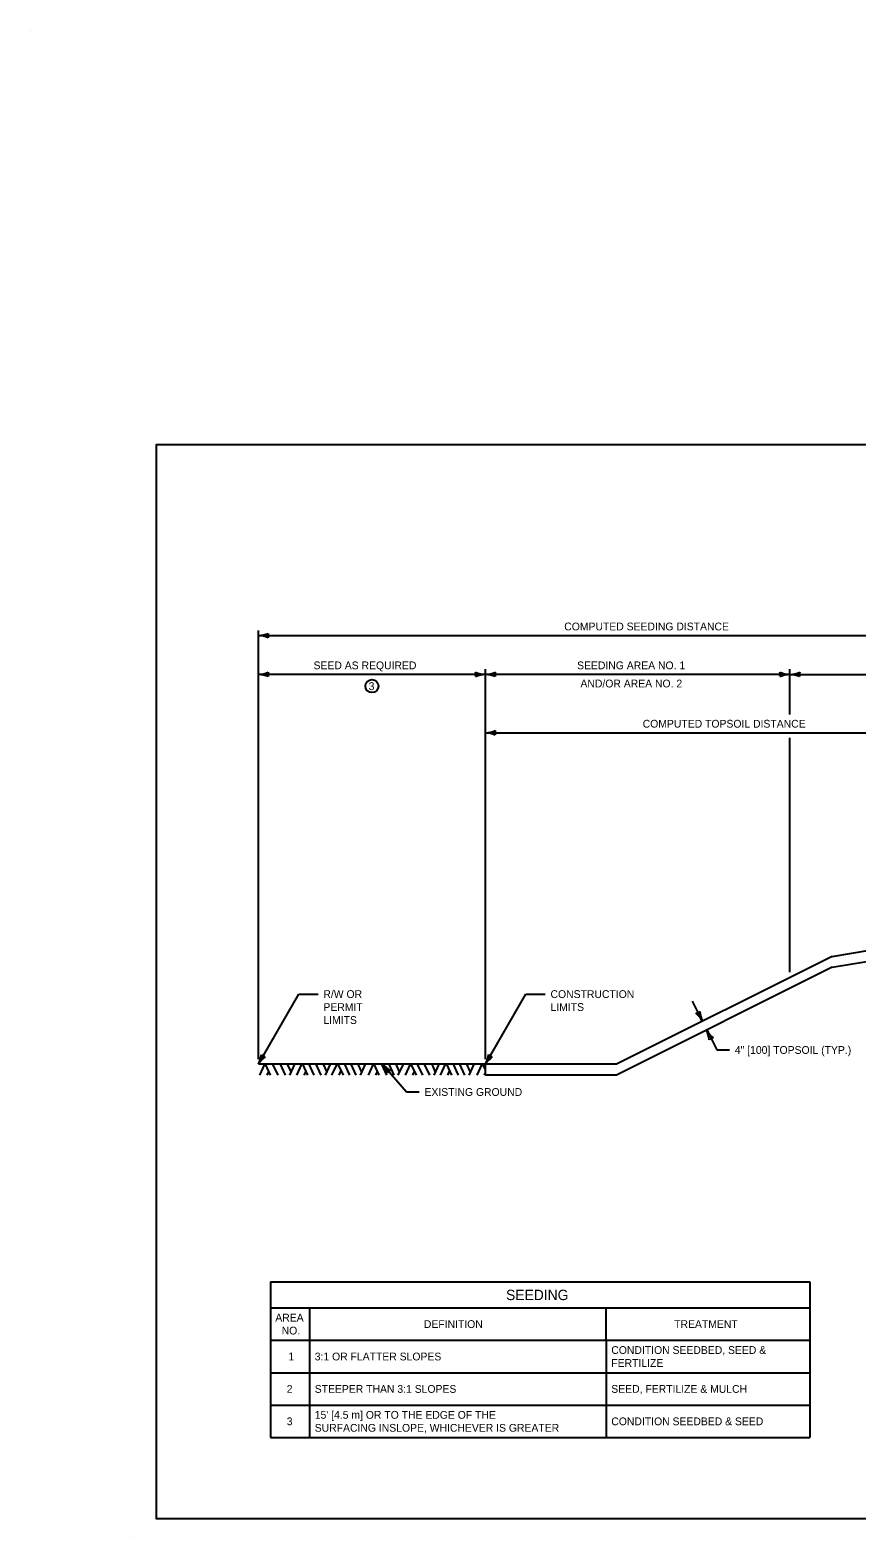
# Model space of a CAD drawing. Extents: x 49991.4 to 50021, y 49987.6 to 50011.4.
# Drawn here: x 50008.76 to 50015.14, y 49999.74 to 50011.36 of the extents above; entities that cross this region are included whole.
import ezdxf

# ---------------------------------------------------------------- set-up
doc = ezdxf.new("R2010")
doc.units = 0
for name, color, linetype in [('Level 1', 7, 'Continuous'), ('Level 2', 7, 'Continuous'), ('Level 3', 7, 'Continuous')]:
    doc.layers.add(name, color=color, linetype=linetype)

msp = doc.modelspace()

# ---------------------------------------------------------------- linework, layer by layer
at = {"layer": 'Level 1'}
for p, q in [((50008.765, 50011.363), (50008.765, 50011.363)), ((50014.951, 50004.136), (50017.132, 50004.5)), ((50014.951, 50004.22), (50016.078, 50004.408)), ((50014.951, 50004.22), (50013.287, 50003.388)), ((50014.951, 50004.136), (50013.287, 50003.304)), ((50013.287, 50003.388), (50010.526, 50003.388)), ((50010.536, 50003.304), (50010.575, 50003.388)), ((50010.62, 50003.304), (50010.58, 50003.388)), ((50010.678, 50003.304), (50010.638, 50003.388)), ((50010.735, 50003.304), (50010.697, 50003.388)), ((50010.777, 50003.329), (50010.75, 50003.388)), ((50010.767, 50003.304), (50010.806, 50003.388)), ((50010.822, 50003.304), (50010.861, 50003.388)), ((50010.906, 50003.304), (50010.867, 50003.388)), ((50010.955, 50003.304), (50010.916, 50003.388)), ((50011.009, 50003.304), (50010.97, 50003.388)), ((50011.055, 50003.328), (50011.027, 50003.388)), ((50011.043, 50003.304), (50011.082, 50003.388)), ((50011.093, 50003.304), (50011.132, 50003.388)), ((50011.181, 50003.304), (50011.142, 50003.388)), ((50011.228, 50003.31), (50011.192, 50003.388)), ((50011.28, 50003.304), (50011.241, 50003.388)), ((50011.324, 50003.327), (50011.296, 50003.388)), ((50011.313, 50003.304), (50011.352, 50003.388)), ((50011.374, 50003.304), (50011.413, 50003.388)), ((50011.458, 50003.304), (50011.419, 50003.388)), ((50011.516, 50003.304), (50011.477, 50003.388)), ((50011.573, 50003.304), (50011.535, 50003.388)), ((50011.615, 50003.329), (50011.588, 50003.388)), ((50011.605, 50003.304), (50011.644, 50003.388)), ((50011.66, 50003.304), (50011.7, 50003.388)), ((50011.744, 50003.304), (50011.705, 50003.388)), ((50011.793, 50003.304), (50011.754, 50003.388)), ((50011.847, 50003.304), (50011.808, 50003.388)), ((50011.893, 50003.328), (50011.865, 50003.388)), ((50011.881, 50003.304), (50011.92, 50003.388)), ((50011.931, 50003.304), (50011.97, 50003.388)), ((50012.019, 50003.304), (50011.98, 50003.388)), ((50012.066, 50003.31), (50012.03, 50003.388)), ((50012.119, 50003.304), (50012.079, 50003.388)), ((50012.162, 50003.327), (50012.134, 50003.388)), ((50012.152, 50003.304), (50012.191, 50003.388)), ((50012.212, 50003.304), (50012.251, 50003.388)), ((50012.277, 50003.344), (50012.257, 50003.388)), ((50012.277, 50003.304), (50012.277, 50003.388)), ((50010.593, 50003.304), (50010.606, 50003.333)), ((50010.879, 50003.304), (50010.893, 50003.333)), ((50011.148, 50003.304), (50011.164, 50003.339)), ((50011.23, 50003.304), (50011.228, 50003.31)), ((50011.431, 50003.304), (50011.445, 50003.333)), ((50011.717, 50003.304), (50011.731, 50003.333)), ((50011.986, 50003.304), (50012.002, 50003.339)), ((50012.069, 50003.304), (50012.066, 50003.31)), ((50012.269, 50003.304), (50012.277, 50003.321)), ((50013.287, 50003.304), (50012.277, 50003.304)), ((50009.537, 49999.736), (50009.537, 49999.736))]:
    msp.add_line(p, q, dxfattribs=at)
msp.add_lwpolyline([(50020.938, 50008.165), (50009.737, 50008.165), (50009.737, 49999.886), (50020.938, 49999.886)], close=True, dxfattribs=at)
at = {"layer": 'Level 2'}
for p, q in [((50010.62, 50001.709), (50010.62, 50001.509)), ((50010.62, 50001.709), (50014.78, 50001.709)), ((50014.78, 50001.709), (50014.78, 50001.509)), ((50010.62, 50001.509), (50010.62, 50001.259)), ((50010.62, 50001.509), (50010.92, 50001.509)), ((50010.92, 50001.509), (50010.92, 50001.259)), ((50010.92, 50001.509), (50012.972, 50001.509)), ((50012.972, 50001.509), (50014.78, 50001.509)), ((50013.208, 50001.259), (50013.208, 50001.509)), ((50014.78, 50001.509), (50014.78, 50001.259)), ((50010.62, 50001.259), (50010.92, 50001.259)), ((50010.62, 50001.259), (50010.62, 50001.009)), ((50010.92, 50001.259), (50010.92, 50001.009)), ((50010.92, 50001.259), (50013.208, 50001.259)), ((50013.208, 50001.259), (50013.208, 50001.009)), ((50013.208, 50001.259), (50014.78, 50001.259)), ((50014.78, 50001.259), (50014.78, 50001.009)), ((50010.62, 50001.009), (50010.92, 50001.009)), ((50010.62, 50001.009), (50010.62, 50000.759)), ((50010.92, 50001.009), (50010.92, 50000.759)), ((50010.92, 50001.009), (50013.208, 50001.009)), ((50013.208, 50001.009), (50013.208, 50000.759)), ((50013.208, 50001.009), (50014.78, 50001.009)), ((50014.78, 50001.009), (50014.78, 50000.759)), ((50010.62, 50000.759), (50010.92, 50000.759)), ((50010.62, 50000.759), (50010.62, 50000.509)), ((50010.92, 50000.759), (50010.92, 50000.509)), ((50010.92, 50000.759), (50013.208, 50000.759)), ((50013.208, 50000.759), (50013.208, 50000.509)), ((50013.208, 50000.759), (50014.78, 50000.759)), ((50014.78, 50000.759), (50014.78, 50000.509)), ((50010.62, 50000.509), (50010.92, 50000.509)), ((50010.92, 50000.509), (50013.208, 50000.509)), ((50013.208, 50000.509), (50014.78, 50000.509))]:
    msp.add_line(p, q, dxfattribs=at)
msp.add_circle((50011.401, 50006.304), 0.05, dxfattribs=at)
at = {"layer": 'Level 3'}
for p, q in [((50010.526, 50003.428), (50010.526, 50006.734)), ((50010.526, 50006.694), (50016.653, 50006.694)), ((50012.277, 50006.394), (50010.526, 50006.394)), ((50012.277, 50003.428), (50012.277, 50006.434)), ((50014.625, 50006.394), (50012.277, 50006.394)), ((50014.625, 50006.084), (50014.625, 50006.434)), ((50014.625, 50006.394), (50016.653, 50006.394)), ((50012.277, 50005.944), (50016.078, 50005.944)), ((50014.625, 50004.098), (50014.625, 50005.904)), ((50010.526, 50003.388), (50010.837, 50003.929)), ((50010.837, 50003.929), (50010.987, 50003.929)), ((50012.277, 50003.388), (50012.589, 50003.929)), ((50012.589, 50003.929), (50012.739, 50003.929)), ((50013.872, 50003.875), (50013.95, 50003.72)), ((50013.984, 50003.653), (50014.061, 50003.498)), ((50014.061, 50003.498), (50014.161, 50003.498)), ((50011.482, 50003.388), (50011.667, 50003.174)), ((50011.667, 50003.174), (50011.767, 50003.174))]:
    msp.add_line(p, q, dxfattribs=at)
for centre, radius, start, end in [((50010.514, 50006.927), 0.233, 272.8273, 292.0772), ((50010.516, 50006.472), 0.222, 67.456, 87.6395), ((50010.654, 50006.694), 0.0548, 162.1388, 197.8612), ((50010.514, 50006.627), 0.233, 272.8273, 292.0772), ((50010.514, 50006.627), 0.233, 272.8273, 292.0772), ((50010.516, 50006.172), 0.222, 67.456, 87.6395), ((50010.516, 50006.172), 0.222, 67.456, 87.6395), ((50010.654, 50006.394), 0.0548, 162.1388, 197.8612), ((50010.654, 50006.394), 0.0548, 162.1388, 197.8612), ((50012.286, 50006.616), 0.222, 247.456, 267.6395), ((50012.149, 50006.394), 0.0548, 342.1388, 17.8612), ((50012.289, 50006.161), 0.233, 92.8273, 112.0772), ((50012.266, 50006.627), 0.233, 272.8273, 292.0772), ((50012.268, 50006.172), 0.222, 67.456, 87.6395), ((50012.405, 50006.394), 0.0548, 162.1388, 197.8612), ((50014.635, 50006.616), 0.222, 247.456, 267.6395), ((50014.497, 50006.394), 0.0548, 342.1388, 17.8612), ((50014.637, 50006.161), 0.233, 92.8273, 112.0772), ((50014.614, 50006.627), 0.233, 272.8273, 292.0772), ((50014.616, 50006.172), 0.222, 67.456, 87.6395), ((50014.754, 50006.394), 0.0548, 162.1388, 197.8612), ((50012.266, 50006.177), 0.233, 272.8273, 292.0772), ((50012.266, 50006.177), 0.233, 272.8273, 292.0772), ((50012.268, 50005.722), 0.222, 67.456, 87.6395), ((50012.268, 50005.722), 0.222, 67.456, 87.6395), ((50012.405, 50005.944), 0.0548, 162.1388, 197.8612), ((50012.405, 50005.944), 0.0548, 162.1388, 197.8612), ((50013.892, 50003.835), 0.0548, 278.7039, 314.4262), ((50013.747, 50003.606), 0.233, 29.3924, 48.6422), ((50014.153, 50003.811), 0.222, 184.0211, 204.2046), ((50013.781, 50003.561), 0.222, 4.0211, 24.2046), ((50014.187, 50003.767), 0.233, 209.3924, 228.6422), ((50013.781, 50003.561), 0.222, 4.0211, 24.2046), ((50014.187, 50003.767), 0.233, 209.3924, 228.6422), ((50014.041, 50003.538), 0.0548, 98.7039, 134.4262), ((50014.041, 50003.538), 0.0548, 98.7039, 134.4262), ((50010.318, 50003.495), 0.233, 332.8273, 352.0772), ((50010.713, 50003.269), 0.222, 127.456, 147.6395), ((50010.59, 50003.5), 0.0548, 222.1388, 257.8612), ((50011.308, 50003.25), 0.222, 18.2538, 38.4373), ((50011.651, 50003.549), 0.233, 223.6251, 242.8749), ((50012.07, 50003.495), 0.233, 332.8273, 352.0772), ((50012.465, 50003.269), 0.222, 127.456, 147.6395), ((50012.341, 50003.5), 0.0548, 222.1388, 257.8612), ((50011.566, 50003.291), 0.0548, 112.9366, 148.659)]:
    msp.add_arc(centre, radius, start, end, dxfattribs=at)

# ---------------------------------------------------------------- texts
at = {"layer": 'Level 2'}
for s, height, p in [('COMPUTED SEEDING DISTANCE', 0.06, (50012.885, 50006.734)), ('SEED AS REQUIRED', 0.06, (50010.951, 50006.434)), ('SEEDING AREA NO. 1', 0.06, (50012.984, 50006.434)), ('3', 0.06, (50011.376, 50006.274)), ('AND/OR AREA NO. 2', 0.06, (50013.01, 50006.294)), ('COMPUTED TOPSOIL DISTANCE', 0.06, (50013.49, 50005.984)), ('R/W OR', 0.06, (50011.027, 50003.899)), ('CONSTRUCTION', 0.06, (50012.779, 50003.899)), ('PERMIT', 0.06, (50011.027, 50003.799)), ('LIMITS', 0.06, (50012.779, 50003.799)), ('LIMITS', 0.06, (50011.027, 50003.699)), ('4" [100] TOPSOIL (TYP.)', 0.06, (50014.201, 50003.468)), ('EXISTING GROUND', 0.06, (50011.807, 50003.144)), ('SEEDING', 0.08, (50012.436, 50001.569)), ('AREA', 0.06, (50010.656, 50001.404)), ('DEFINITION', 0.06, (50011.802, 50001.354)), ('TREATMENT', 0.06, (50013.733, 50001.354)), ('NO.', 0.06, (50010.705, 50001.304)), ('1', 0.06, (50010.757, 50001.104)), ('3:1 OR FLATTER SLOPES', 0.06, (50010.96, 50001.104)), ('CONDITION SEEDBED, SEED &', 0.06, (50013.248, 50001.154)), ('FERTILIZE', 0.06, (50013.248, 50001.054)), ('2', 0.06, (50010.744, 50000.854)), ('STEEPER THAN 3:1 SLOPES', 0.06, (50010.96, 50000.854)), ('SEED, FERTILIZE & MULCH', 0.06, (50013.248, 50000.854)), ("15' [4.5 m] OR TO THE EDGE OF THE ", 0.06, (50010.96, 50000.654)), ('3', 0.06, (50010.744, 50000.604)), ('SURFACING INSLOPE, WHICHEVER IS GREATER', 0.06, (50010.96, 50000.554)), ('CONDITION SEEDBED & SEED', 0.06, (50013.248, 50000.604))]:
    msp.add_text(s, height=height, dxfattribs=at).set_placement(p)

doc.saveas('drawing.dxf')
